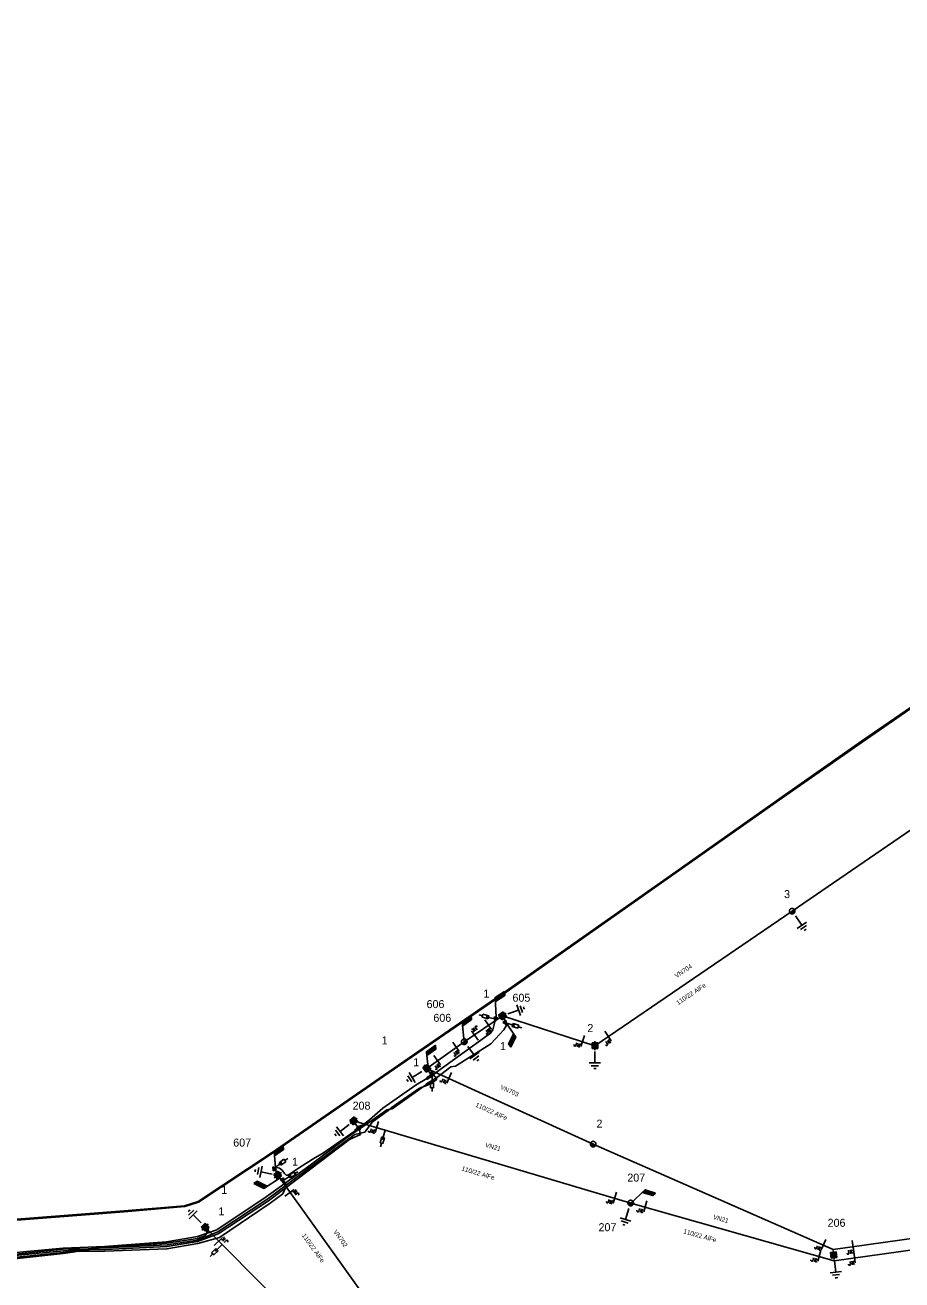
# Model space of a CAD drawing. Extents: x -545588 to -543214, y -1196037 to -1194452.
# Drawn here: x -545200.6 to -545008.8, y -1194905.8 to -1194631.4 of the extents above; entities that cross this region are included whole.
import ezdxf

# ---------------------------------------------------------------- set-up
doc = ezdxf.new("R2010")
doc.units = 0
for name, color, linetype in [('Default', 7, 'Continuous'), ('Vrstva 1', 7, 'Continuous'), ('Vrstva 11', 7, 'Continuous'), ('Vrstva 12', 7, 'Continuous'), ('Vrstva 13', 7, 'Continuous'), ('Vrstva 14', 7, 'Continuous'), ('Vrstva 15', 7, 'Continuous'), ('Vrstva 16', 7, 'Continuous'), ('Vrstva 18', 7, 'Continuous'), ('Vrstva 19', 7, 'Continuous'), ('Vrstva 2', 7, 'Continuous'), ('Vrstva 20', 7, 'Continuous'), ('Vrstva 3', 7, 'Continuous'), ('Vrstva 4', 7, 'Continuous'), ('Vrstva 5', 7, 'Continuous'), ('Vrstva 52', 7, 'Continuous')]:
    doc.layers.add(name, color=color, linetype=linetype)

# ---------------------------------------------------------------- blocks, each defined once
blk = doc.blocks.new('VN840')
at = {"layer": 'Vrstva 15'}
for points in [[(-0.01, 1.41), (-0.01, -1.09)], [(-1.51, -1.24), (-1.51, -1.15)], [(-1.48, -1.35), (-1.51, -1.24)], [(-1.33, -1.42), (-1.48, -1.35)], [(-1.27, -1.42), (-1.33, -1.42)], [(-1.13, -1.35), (-1.27, -1.42)], [(-1.09, -1.24), (-1.13, -1.35)], [(-1.09, -0.59), (-1.09, -1.24)], [(-0.68, -0.59), (-0.68, -1.42)], [(-0.68, -1.11), (-0.27, -0.59)], [(-0.54, -0.94), (-0.2, -1.42)]]:
    blk.add_lwpolyline(points, dxfattribs=at)
blk = doc.blocks.new('VN440')
at = {"layer": 'Vrstva 2'}
for points in [[(1.22, 0), (1.21, 0.13), (1.19, 0.25), (1.16, 0.38), (1.11, 0.5), (1.05, 0.61), (0.98, 0.72), (0.9, 0.82), (0.81, 0.91), (0.71, 0.99), (0.6, 1.06), (0.49, 1.12), (0.37, 1.16), (0.25, 1.2), (0.12, 1.22), (-0.01, 1.22), (-0.14, 1.22), (-0.26, 1.2), (-0.39, 1.16), (-0.51, 1.12), (-0.62, 1.06), (-0.73, 0.99), (-0.83, 0.91), (-0.92, 0.82), (-1, 0.72), (-1.07, 0.61), (-1.13, 0.5), (-1.18, 0.38), (-1.21, 0.25), (-1.23, 0.13), (-1.24, 0), (-1.23, -0.13), (-1.21, -0.26), (-1.18, -0.38), (-1.13, -0.5), (-1.07, -0.62), (-1, -0.73), (-0.92, -0.83), (-0.83, -0.92), (-0.73, -1), (-0.62, -1.07), (-0.51, -1.13), (-0.39, -1.17), (-0.26, -1.2), (-0.14, -1.23), (-0.01, -1.23), (0.12, -1.23), (0.25, -1.2), (0.37, -1.17), (0.49, -1.13), (0.6, -1.07), (0.71, -1), (0.81, -0.92), (0.9, -0.83), (0.98, -0.73), (1.05, -0.62), (1.11, -0.5), (1.16, -0.38), (1.19, -0.26), (1.21, -0.13), (1.22, 0)], [(-1.24, 0), (1.22, 0)], [(-1.18, -0.34), (1.1, -0.34)], [(-1.01, -0.63), (0.97, -0.63)], [(-0.74, -0.92), (0.68, -0.92)]]:
    blk.add_lwpolyline(points, dxfattribs=at)
blk = doc.blocks.new('VN890')
at = {"layer": 'Vrstva 4'}
for points in [[(-0.41, 0.41), (0.41, 0)], [(-0.41, -0.41), (-0.41, 0.41)], [(0.41, 0), (-0.41, -0.41)], [(-0.34, 0.31), (0.27, 0), (-0.34, -0.3), (-0.34, 0.31)], [(-0.26, 0.2), (0.1, 0), (-0.26, -0.18), (-0.26, 0.2)], [(-0.19, 0.09), (-0.04, 0), (-0.19, -0.08), (-0.19, 0.09)], [(-0.16, -0.01), (-0.16, 0.03), (-0.13, 0.01), (-0.16, -0.01)]]:
    blk.add_lwpolyline(points, dxfattribs=at)
blk = doc.blocks.new('VN820')
at = {"layer": 'Vrstva 13'}
for points in [[(0, 0), (0, -2.1)], [(-0.32, -1.63), (0.34, -1.63)], [(-0.32, -2.95), (-0.32, -1.63)], [(0, -2.1), (-0.12, -1.86)], [(0, -2.1), (0.12, -1.86)], [(0.34, -1.63), (0.34, -2.95)], [(0.34, -2.95), (-0.32, -2.95)], [(0, -2.95), (0, -3.75)]]:
    blk.add_lwpolyline(points, dxfattribs=at)
blk = doc.blocks.new('VN810')
at = {"layer": 'Vrstva 14'}
for points in [[(0, -1.25), (0, -3.75)], [(1.25, -3.75), (-1.25, -3.75)], [(0.77, -4.37), (-0.8, -4.37)], [(0, -5), (-0.25, -5)], [(0.27, -5), (0, -5)]]:
    blk.add_lwpolyline(points, dxfattribs=at)
blk = doc.blocks.new('VN001')
at = {"layer": 'Default'}
for p, q in [((1.73, 3.03), (4.14, 3.03)), ((1.76, 3.08), (4.17, 3.08)), ((1.79, 3.13), (4.2, 3.13)), ((1.82, 3.18), (4.23, 3.18)), ((1.85, 3.23), (4.26, 3.23)), ((1.87, 3.28), (4.29, 3.28)), ((1.9, 3.33), (4.32, 3.33)), ((1.93, 3.38), (4.35, 3.38)), ((1.96, 3.43), (4.37, 3.43)), ((1.99, 3.48), (4.4, 3.48)), ((2.02, 3.53), (4.43, 3.53)), ((2.05, 3.58), (4.46, 3.58)), ((2.07, 3.63), (4.49, 3.63)), ((2.1, 3.68), (4.52, 3.68)), ((2.13, 3.73), (2.54, 3.73))]:
    blk.add_line(p, q, dxfattribs=at)
blk.add_lwpolyline([(2.13, 3.73), (0, 0)], dxfattribs=at)
blk.add_lwpolyline([(4.55, 3.73), (2.13, 3.73), (1.7, 2.98), (4.12, 2.99)], close=True, dxfattribs=at)
blk = doc.blocks.new('VN470')
at = {"layer": 'Vrstva 2'}
for points in [[(-1.23, 1.22), (1.23, 1.22)], [(-1.23, -1.23), (-1.23, 1.22)], [(-0.92, 0.9), (0.92, 0.9)], [(-0.92, -0.95), (-0.92, 0.9)], [(-0.61, 0.61), (0.61, 0.61)], [(-0.61, -0.62), (-0.61, 0.61)], [(-0.31, -0.27), (-0.31, 0.34)], [(-0.31, 0.34), (0.31, 0.34)], [(0, 1.22), (0, 1.97)], [(0.31, 0.34), (0.31, -0.27)], [(0.61, 0.61), (0.61, -0.62)], [(0.92, 0.9), (0.92, -0.95)], [(1.23, 1.22), (1.23, -1.23)], [(1.23, -1.23), (-1.23, -1.23)], [(0.92, -0.95), (-0.92, -0.95)], [(0.61, -0.62), (-0.61, -0.62)], [(0.31, -0.27), (-0.31, -0.27)], [(0, -1.23), (0, -1.98)]]:
    blk.add_lwpolyline(points, dxfattribs=at)

msp = doc.modelspace()

# ---------------------------------------------------------------- linework, layer by layer
at = {"layer": 'Vrstva 1'}
for points in [[(-545096.16, -1194848.04), (-545075.95, -1194854.58), (-545032.81, -1194825.14), (-544993.69, -1194798.32), (-544903.01, -1194736.22), (-544804.37, -1194669.21), (-544702.68, -1194600.1), (-544611.95, -1194519.78), (-544514.29, -1194451.62)], [(-544083.88, -1194767.33), (-544137.68, -1194774.97), (-544275.32, -1194794.17), (-544399.3, -1194811.66), (-544539.71, -1194831.51), (-544666.5, -1194849.29), (-544797.03, -1194867.27), (-544922.4, -1194884.94), (-545023.84, -1194899.15), (-545076.32, -1194876.08), (-545112.71, -1194859.53)], [(-545068.12, -1194888.96), (-545023.6, -1194901.6), (-544922.06, -1194887.4), (-544796.64, -1194869.77), (-544666.32, -1194851.78), (-544539.47, -1194833.99), (-544398.96, -1194814.1), (-544275.11, -1194796.62), (-544137.43, -1194777.48), (-544081.81, -1194769.58)], [(-545128.71, -1194871), (-545121.79, -1194873.05), (-545068.12, -1194888.96)], [(-545145.32, -1194882.87), (-545144.58, -1194883.9), (-545122.79, -1194914.35), (-545087.98, -1194964.09)], [(-545125.62, -1194930.15), (-545157.44, -1194897.99), (-545161.19, -1194894.21)]]:
    msp.add_lwpolyline(points, dxfattribs=at)
at = {"layer": 'Vrstva 20'}
for points in [[(-545112.81, -1194861.62), (-545111.28, -1194860.66), (-545111.12, -1194860.92), (-545112.65, -1194861.88)], [(-545128.49, -1194873.07), (-545127.02, -1194871.95), (-545126.84, -1194872.19), (-545128.31, -1194873.31)]]:
    msp.add_lwpolyline(points, close=True, dxfattribs=at)
at = {"layer": 'Vrstva 5'}
for points in [[(-545233.41, -1194894.88), (-545178.88, -1194890.69), (-545165.68, -1194889.55), (-545162.68, -1194888.62), (-545146.55, -1194877.89), (-545122.2, -1194861.06), (-545095.47, -1194842.73), (-545060.25, -1194817.94), (-545034.96, -1194800.14), (-545017.61, -1194788.01), (-544994.8, -1194772.3), (-544991.56, -1194771.33), (-544987.81, -1194767.38), (-544970.95, -1194755.62), (-544959.46, -1194747.69), (-544955.77, -1194745.88), (-544943.24, -1194736.48), (-544921.65, -1194721.82), (-544915.98, -1194718.78), (-544907.91, -1194712.46), (-544897.39, -1194705.06), (-544885.31, -1194696.62), (-544879.55, -1194692.83), (-544879.87, -1194692.29)], [(-545233.4, -1194895.08), (-545178.86, -1194890.89), (-545165.64, -1194889.75), (-545162.6, -1194888.8), (-545146.43, -1194878.05), (-545122.08, -1194861.22), (-545095.35, -1194842.89), (-545060.13, -1194818.1), (-545034.84, -1194800.3), (-545017.49, -1194788.17), (-544994.72, -1194772.48)], [(-545095.79, -1194848.6), (-545095.53, -1194849.57), (-545095.36, -1194850.24), (-545095.83, -1194851.09), (-545098.73, -1194854.12), (-545106.42, -1194859.04), (-545107.48, -1194859.18), (-545110.61, -1194861.57), (-545112.8, -1194862.88), (-545113.45, -1194863.46), (-545114.26, -1194864.07), (-545120.29, -1194868.36), (-545120.89, -1194868.47), (-545121.42, -1194868.57), (-545124.71, -1194870.88), (-545129.84, -1194874.43), (-545138.8, -1194881.11), (-545147.81, -1194887.61), (-545158.6, -1194894.81), (-545162.87, -1194896.28), (-545169.61, -1194897.45), (-545183.17, -1194898.43), (-545186.8, -1194898.6), (-545192.24, -1194898.85), (-545208.93, -1194900.39)], [(-545097.56, -1194848.31), (-545097.68, -1194848.78), (-545098.24, -1194851.06), (-545098.81, -1194851.8), (-545109.76, -1194859.75), (-545111.2, -1194860.79), (-545112.73, -1194861.75), (-545115.02, -1194863.14), (-545122.33, -1194868.25), (-545125.21, -1194870.74), (-545126.93, -1194872.07), (-545128.4, -1194873.19), (-545135.55, -1194878.12), (-545137.2, -1194879.11), (-545140.55, -1194881.18), (-545143.03, -1194882.86), (-545143.47, -1194882.86), (-545143.86, -1194882.51), (-545144.35, -1194881.8), (-545144.93, -1194881.35), (-545145.48, -1194881.2), (-545146.16, -1194881.36), (-545145.73, -1194882.07)], [(-545112.33, -1194860.15), (-545111.56, -1194860.79), (-545110.61, -1194861.57), (-545110.58, -1194861.99), (-545112.59, -1194863.17), (-545113.74, -1194863.61), (-545114.34, -1194863.84), (-545120.48, -1194868.18), (-545120.68, -1194868.39), (-545121.19, -1194868.73), (-545124.66, -1194871.31), (-545126.29, -1194873.47), (-545128.43, -1194874.01), (-545129.75, -1194874.9), (-545138.56, -1194881.39), (-545147.45, -1194888.07), (-545158.4, -1194895.27), (-545162.84, -1194897.08), (-545169.49, -1194898.08), (-545183.12, -1194898.78), (-545186.75, -1194898.94), (-545192.21, -1194899.03), (-545208.9, -1194900.78)], [(-545128.71, -1194871), (-545128.35, -1194871.62), (-545127.51, -1194872.65), (-545127.21, -1194873.94), (-545129.58, -1194875.1), (-545138.37, -1194881.68), (-545147.33, -1194888.47), (-545158.32, -1194895.7), (-545162.82, -1194897.39), (-545169.52, -1194898.44), (-545183.07, -1194899.14), (-545189.95, -1194899.24), (-545192.17, -1194899.42), (-545208.95, -1194900.99)], [(-545144.76, -1194883.43), (-545144.15, -1194884.04), (-545143.79, -1194884.4), (-545143.4, -1194885.15), (-545144.22, -1194886.95), (-545146.97, -1194889.02), (-545158.05, -1194896.49), (-545162.81, -1194897.81), (-545169.54, -1194898.98), (-545183.1, -1194899.45), (-545188.58, -1194899.56), (-545190.38, -1194899.49), (-545192.21, -1194899.78), (-545208.91, -1194901.48)], [(-545161.19, -1194894.21), (-545160.85, -1194894.72), (-545160.77, -1194895.02), (-545160.69, -1194895.33), (-545161.24, -1194896.13), (-545162.82, -1194896.69), (-545169.61, -1194897.77), (-545183.13, -1194898.59), (-545185.37, -1194898.78), (-545189.67, -1194899.61), (-545192.22, -1194899.97), (-545208.89, -1194901.81)]]:
    msp.add_lwpolyline(points, dxfattribs=at)
at = {"layer": 'Vrstva 52'}
for points in [[(-545096.16, -1194848.04), (-545104.5, -1194853.69)], [(-545104.5, -1194853.69), (-545112.71, -1194859.53)]]:
    msp.add_lwpolyline(points, dxfattribs=at)

# ---------------------------------------------------------------- block references
at = {"layer": 'Vrstva 11'}
for p, rotation in [((-545097.56, -1194848.31), 32.096245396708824), ((-545104.5, -1194853.69), 36.02518610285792), ((-545095.64, -1194849.15), -116.71277724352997), ((-545112.33, -1194860.15), 35.81319731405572), ((-545145.73, -1194882.07), 34.68804711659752), ((-545144.76, -1194883.43), 152.8339916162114), ((-545068.12, -1194888.96), -17.48817510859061)]:
    msp.add_blockref('VN001', p, dxfattribs=dict(at, rotation=rotation))
at = {"layer": 'Vrstva 13'}
for name, p, xscale, yscale, rotation in [('VN440', (-545032.81, -1194825.14), 0.5000000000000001, 0.5, 34.61069446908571), ('VN470', (-545096.16, -1194848.04), 0.49999999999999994, 0.5000000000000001, -55.38930558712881), ('VN440', (-545104.5, -1194853.69), 0.5, 0.5, 36.02518610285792), ('VN470', (-545075.95, -1194854.58), 0.49999999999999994, 0.5000000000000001, 179.99069427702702), ('VN470', (-545112.71, -1194859.53), 0.49999999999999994, 0.5000000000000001, 33.63840834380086), ('VN470', (-545128.71, -1194871), 0.5, 0.5, 127.72969997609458), ('VN440', (-545076.32, -1194876.08), 0.5000000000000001, 0.5, -24.236872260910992), ('VN470', (-545145.32, -1194882.87), 0.5, 0.5, 125.59545280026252), ('VN440', (-545068.12, -1194888.96), 0.5, 0.5, -17.48817510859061), ('VN470', (-545161.19, -1194894.21), 0.49999999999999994, 0.49999999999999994, 134.70209442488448), ('VN470', (-545023.71, -1194900.32), 0.49999999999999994, 0.4999999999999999, 6.796644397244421)]:
    msp.add_blockref(name, p, dxfattribs=dict(at, xscale=xscale, yscale=yscale, rotation=rotation))
at = {"layer": 'Vrstva 15'}
for p, rotation in [((-545032.81, -1194825.14), 34.61069446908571), ((-545096.16, -1194848.04), 109.73254112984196), ((-545104.5, -1194853.69), 36.02581938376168), ((-545075.95, -1194854.58), -0.009305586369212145), ((-545112.71, -1194859.53), -58.06982772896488), ((-545128.71, -1194871), -52.2275944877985), ((-545145.32, -1194882.87), -101.57163605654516), ((-545161.19, -1194894.21), -135.44435002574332), ((-545068.12, -1194888.96), -17.488175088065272), ((-545023.71, -1194900.32), 6.796644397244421)]:
    msp.add_blockref('VN810', p, dxfattribs=dict(at, rotation=rotation))
at = {"layer": 'Vrstva 16'}
for p, rotation in [((-545097.66, -1194848.74), -104.41971112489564), ((-545095.53, -1194849.57), 73.2599749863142), ((-545111.56, -1194860.79), 0.09709432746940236), ((-545121.79, -1194873.05), -16.502700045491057), ((-545146.16, -1194881.36), 125.125952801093), ((-545144.15, -1194884.04), 120.75388891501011), ((-545157.44, -1194897.99), -45.30478607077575)]:
    msp.add_blockref('VN820', p, dxfattribs=dict(at, rotation=rotation))
at = {"layer": 'Vrstva 18'}
for p, rotation in [((-545099.19, -1194850.09), 34.116055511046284), ((-545102.3, -1194852.2), -145.88552772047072), ((-545078.67, -1194853.7), -17.916263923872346), ((-545072.99, -1194852.56), 34.31077225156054), ((-545106.22, -1194854.91), 35.425294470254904), ((-545110.31, -1194857.82), 35.425294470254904), ((-545107.88, -1194861.73), -24.455816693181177), ((-545123.65, -1194872.5), -16.51080007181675), ((-545142.62, -1194886.64), 125.59358056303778), ((-545071.63, -1194887.93), -16.350033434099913), ((-545064.96, -1194889.86), -15.847444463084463), ((-545158.2, -1194897.23), 134.69061664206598), ((-545026, -1194898.2), -23.7348555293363), ((-545026.91, -1194900.66), -15.847444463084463), ((-545019.49, -1194898.54), 7.976258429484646), ((-545019.15, -1194900.98), 7.96286939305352)]:
    msp.add_blockref('VN840', p, dxfattribs=dict(at, rotation=rotation))
at = {"layer": 'Vrstva 19'}
for p, rotation in [((-545097.68, -1194848.78), -104.41971109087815), ((-545095.53, -1194849.57), -54.63753888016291), ((-545111.56, -1194860.79), -56.548316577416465), ((-545127.51, -1194872.65), -53.087622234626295), ((-545146.16, -1194881.36), 121.38319165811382), ((-545144.15, -1194884.04), -54.79701672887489), ((-545160.77, -1194895.01), -80.36246111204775)]:
    msp.add_blockref('VN890', p, dxfattribs=dict(at, rotation=rotation))

# ---------------------------------------------------------------- texts
at = {"layer": 'Vrstva 12'}
for s, p in [('605', (-545093.97, -1194844.95)), ('606', (-545112.76, -1194846.34)), ('1', (-545122.6, -1194854.28)), ('1', (-545096.71, -1194855.53)), ('607', (-545155.04, -1194876.62)), ('1', (-545157.67, -1194886.98)), ('207', (-545075.15, -1194895.12))]:
    msp.add_text(s, height=1.75, dxfattribs=at).set_placement(p)
at = {"layer": 'Vrstva 14'}
for s, p in [('3', (-545034.58, -1194822.29)), ('1', (-545100.32, -1194844.03)), ('606', (-545111.27, -1194849.34)), ('2', (-545077.6, -1194851.58)), ('1', (-545115.67, -1194859.04)), ('208', (-545128.93, -1194868.54)), ('2', (-545075.6, -1194872.48)), ('1', (-545142.18, -1194880.79)), ('207', (-545068.86, -1194884.28)), ('1', (-545158.28, -1194891.64)), ('206', (-545025.05, -1194894.16))]:
    msp.add_text(s, height=1.75, dxfattribs=at).set_placement(p)
at = {"layer": 'Vrstva 2'}
for rotation, p in [(33.492, (-545057.74, -1194845.72)), (335.544, (-545102.17, -1194867.83)), (343.489, (-545105.19, -1194881.82)), (305.591, (-545140.11, -1194896.05)), (344.153, (-545056.68, -1194895.56))]:
    msp.add_text('110/22 AlFe', height=1, rotation=rotation, dxfattribs=at).set_placement(p)
at = {"layer": 'Vrstva 3'}
for s, rotation, p in [('VN704', 33.69, (-545058.08, -1194839.81)), ('VN703', 335.544, (-545096.73, -1194864)), ('VN21', 343.489, (-545100.01, -1194876.67)), ('VN21', 344.153, (-545050.19, -1194892.43)), ('VN702', 305.591, (-545133.21, -1194895.28))]:
    msp.add_text(s, height=1, rotation=rotation, dxfattribs=at).set_placement(p)

doc.saveas('drawing.dxf')
